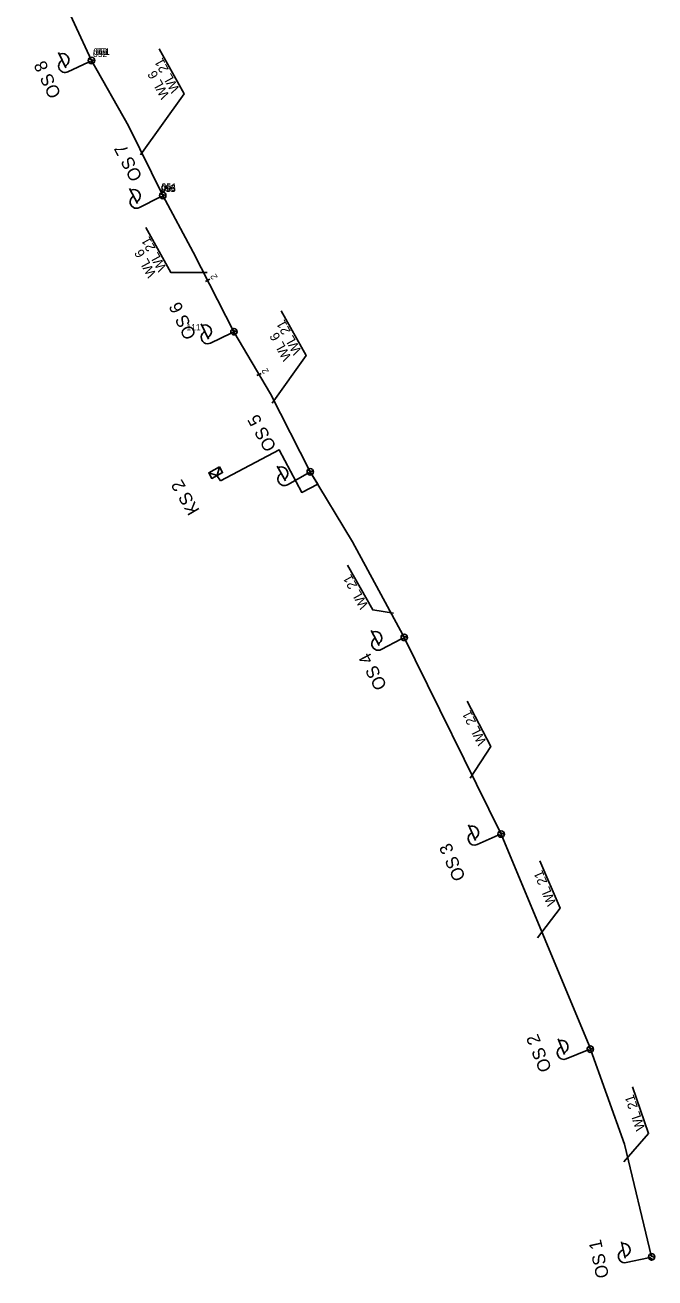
# Model space of a CAD drawing. Extents: x -695448 to -695200, y -1124997 to -1123857.
# Drawn here: x -695414.3 to -695315.4, y -1124997.5 to -1124800.8 of the extents above; entities that cross this region are included whole.
import ezdxf

# ---------------------------------------------------------------- set-up
doc = ezdxf.new("R2010")
doc.units = 0
doc.layers.add('Vrstva 26', color=7, linetype='Continuous')

msp = doc.modelspace()

# ---------------------------------------------------------------- linework, layer by layer
at = {"layer": 'Vrstva 26'}
for p, q in [((-695407.9, -1124807.52), (-695409.05, -1124805.12)), ((-695404.36, -1124806.62), (-695407.59, -1124808.16)), ((-695403.56, -1124806.77), (-695404.41, -1124806.47)), ((-695403.39, -1124806.42), (-695404.32, -1124806.1)), ((-695396.66, -1124828.83), (-695397.9, -1124826.47)), ((-695393.16, -1124827.81), (-695396.33, -1124829.46)), ((-695392.35, -1124827.93), (-695393.21, -1124827.66)), ((-695392.2, -1124827.58), (-695393.13, -1124827.29)), ((-695385.97, -1124841.04), (-695385.31, -1124840.69)), ((-695385.51, -1124850.1), (-695386.67, -1124847.71)), ((-695381.98, -1124849.17), (-695385.19, -1124850.74)), ((-695381.17, -1124849.32), (-695382.02, -1124849.03)), ((-695381.01, -1124848.97), (-695381.93, -1124848.65)), ((-695377.93, -1124855.84), (-695377.26, -1124855.48)), ((-695373.45, -1124872.35), (-695374.76, -1124870.04)), ((-695384.19, -1124871.52), (-695383.64, -1124872.33)), ((-695369.99, -1124871.2), (-695373.1, -1124872.97)), ((-695369.17, -1124871.3), (-695370.04, -1124871.06)), ((-695369.03, -1124870.94), (-695369.98, -1124870.68)), ((-695358.72, -1124898.2), (-695359.97, -1124895.85)), ((-695355.23, -1124897.16), (-695358.39, -1124898.83)), ((-695354.41, -1124897.28), (-695355.27, -1124897.02)), ((-695354.27, -1124896.93), (-695355.2, -1124896.64)), ((-695343.61, -1124928.79), (-695344.69, -1124926.36)), ((-695340.05, -1124927.99), (-695343.32, -1124929.44)), ((-695339.25, -1124928.17), (-695340.09, -1124927.85)), ((-695339.07, -1124927.83), (-695339.99, -1124927.48)), ((-695329.63, -1124962.41), (-695330.62, -1124959.95)), ((-695326.04, -1124961.73), (-695329.36, -1124963.08)), ((-695325.25, -1124961.94), (-695326.07, -1124961.59)), ((-695325.06, -1124961.6), (-695325.96, -1124961.22)), ((-695320.08, -1124994.36), (-695320.66, -1124991.77)), ((-695315.45, -1124994.3), (-695316.27, -1124993.78)), ((-695316.43, -1124994.28), (-695319.93, -1124995.06)), ((-695315.68, -1124994.61), (-695316.44, -1124994.13))]:
    msp.add_line(p, q, dxfattribs=at)
for points in [[(-695414.32, -1124784.79), (-695409.22, -1124794.8), (-695403.9, -1124806.39), (-695398.06, -1124816.61), (-695392.71, -1124827.57), (-695387.95, -1124836.45), (-695381.52, -1124848.94), (-695375.78, -1124858.72), (-695369.54, -1124870.95), (-695362.93, -1124881.95), (-695355.02, -1124896.53), (-695339.58, -1124927.79), (-695325.73, -1124960.98), (-695320.19, -1124976.48), (-695315.94, -1124994.16)], [(-695383.64, -1124872.33), (-695374.4, -1124867.5), (-695370.88, -1124874.17), (-695368.38, -1124872.89), (-695369.54, -1124870.95), (-695375.78, -1124858.72), (-695381.52, -1124848.94), (-695387.95, -1124836.45), (-695392.71, -1124827.57), (-695398.06, -1124816.61), (-695403.9, -1124806.39), (-695409.22, -1124794.8)], [(-695396.19, -1124821.17), (-695389.36, -1124811.59), (-695393.28, -1124804.56)], [(-695385.75, -1124839.64), (-695391.44, -1124839.64), (-695395.35, -1124832.6)], [(-695375.55, -1124860.18), (-695370.21, -1124852.69), (-695374.13, -1124845.65)], [(-695383.8, -1124870.17), (-695384.16, -1124871.51), (-695385.48, -1124871.09)], [(-695356.48, -1124893.12), (-695359.73, -1124892.62), (-695363.68, -1124885.6)], [(-695344.46, -1124919), (-695341.21, -1124914.07), (-695344.89, -1124906.91)], [(-695333.89, -1124944.1), (-695330.32, -1124939.4), (-695333.5, -1124932.01)], [(-695320.32, -1124979.23), (-695316.43, -1124974.81), (-695318.97, -1124967.47)]]:
    msp.add_lwpolyline(points, dxfattribs=at)
msp.add_lwpolyline([(-695383.8, -1124870.17), (-695385.48, -1124871.09), (-695385, -1124871.97), (-695383.32, -1124871.05)], close=True, dxfattribs=at)
for centre in [(-695403.9, -1124806.39), (-695403.9, -1124806.39), (-695392.71, -1124827.57), (-695392.71, -1124827.57), (-695381.52, -1124848.94), (-695381.52, -1124848.94), (-695369.54, -1124870.95), (-695369.54, -1124870.95), (-695354.78, -1124896.92), (-695354.78, -1124896.92), (-695339.58, -1124927.79), (-695339.58, -1124927.79), (-695325.57, -1124961.54), (-695325.57, -1124961.54), (-695315.94, -1124994.16), (-695315.94, -1124994.16)]:
    msp.add_circle(centre, 0.511, dxfattribs=at)
for centre, start, end in [((-695408.03, -1124807.24), 115.649, 295.649), ((-695408.46, -1124806.32), 294.9464, 116.3516), ((-695397.27, -1124827.65), 296.9015, 118.3066), ((-695396.81, -1124828.56), 117.6041, 297.6041), ((-695386.08, -1124848.9), 295.3286, 116.7338), ((-695385.64, -1124849.82), 116.0312, 296.0312), ((-695374.1, -1124871.19), 298.8679, 120.273), ((-695373.6, -1124872.08), 119.5705, 299.5705), ((-695358.87, -1124897.93), 117.9141, 297.9141), ((-695359.34, -1124897.02), 297.2115, 118.6167), ((-695344.14, -1124927.57), 293.1704, 114.5755), ((-695343.73, -1124928.51), 113.873, 293.873), ((-695330.11, -1124961.18), 291.327, 112.7321), ((-695329.74, -1124962.13), 112.0295, 292.0295), ((-695320.36, -1124993.06), 281.9348, 103.34), ((-695320.15, -1124994.06), 102.6374, 282.6374)]:
    msp.add_arc(centre, 1.02, start, end, dxfattribs=at)

# ---------------------------------------------------------------- texts
for s, p in [('052', (-695403.65, -1124805.84)), ('049', (-695403.6, -1124805.48)), ('050', (-695403.6, -1124805.48)), ('051', (-695403.26, -1124805.49)), ('055', (-695393.04, -1124826.99)), ('054', (-695392.9, -1124826.64)), ('053', (-695392.9, -1124826.82)), ('056', (-695392.9, -1124827.01)), ('111', (-695388.98, -1124848.75))]:
    msp.add_text(s, height=1, dxfattribs=at).set_placement(p)
for s, height, rotation, p in [('OS 8', 2, 115.3544, (-695408.62, -1124811.72)), ('WL 21', 1.5, 118.6908, (-695390, -1124810.92)), ('WL 6', 1.5, 118.6908, (-695391.61, -1124811.89)), ('OS 7', 2, 117.3095, (-695395.85, -1124824.7)), ('WL 21', 1.5, 118.6908, (-695392.07, -1124838.97)), ('WL 6', 1.5, 118.6908, (-695393.68, -1124839.93)), ('2', 1, 118.3586, (-695384.06, -1124840.41)), ('OS 6', 2, 115.7366, (-695387.38, -1124849.57)), ('WL 21', 1.5, 118.6908, (-695370.85, -1124852.02)), ('WL 6', 1.5, 118.6908, (-695372.45, -1124852.99)), ('2', 1, 118.3586, (-695376.01, -1124855.2)), ('OS 5', 2, 119.2759, (-695374.79, -1124867.04)), ('KS 2', 2, 120.3168, (-695386.85, -1124876.98)), ('WL 21', 1.5, 118.9593, (-695360.37, -1124891.95)), ('OS 4', 2, 117.6195, (-695357.44, -1124904.56)), ('WL 21', 1.5, 116.7488, (-695341.83, -1124913.38)), ('OS 3', 2, 113.5784, (-695345.11, -1124934.63)), ('WL 21', 1.5, 112.8589, (-695330.89, -1124938.67)), ('OS 2', 2, 111.735, (-695331.59, -1124964.68)), ('WL 21', 1.5, 108.7393, (-695316.94, -1124974.04)), ('OS 1', 2, 102.3428, (-695322.62, -1124997.26))]:
    msp.add_text(s, height=height, rotation=rotation, dxfattribs=at).set_placement(p)

doc.saveas('drawing.dxf')
